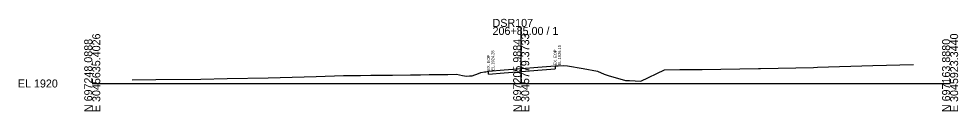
# Model space of a CAD drawing. Extents: x -26 to 19003, y -31 to 24541.
# Drawn here: x 1974.3 to 2302.8, y 15990.3 to 16022.6 of the extents above; entities that cross this region are included whole.
import ezdxf

# ---------------------------------------------------------------- set-up
doc = ezdxf.new("R2010")
doc.units = 0
for name, color, linetype in [('DESIGN - SHEET - Light Grid', 7, 'Continuous'), ('SURVEY - GROUND - Existing Pavement Layer', 7, 'Continuous'), ('SURVEY - GROUND - Existing Pavement Text', 7, 'Continuous'), ('SURVEY - GROUND - Top of Ground', 7, 'Continuous')]:
    doc.layers.add(name, color=color, linetype=linetype)

msp = doc.modelspace()

# ---------------------------------------------------------------- linework, layer by layer
at = {"layer": 'DESIGN - SHEET - Light Grid'}
for p, q in [((2150, 16000), (2150, 16019.79)), ((2000, 16000), (2150, 16000)), ((2150, 16000), (2300, 16000))]:
    msp.add_line(p, q, dxfattribs=at)
at = {"layer": 'SURVEY - GROUND - Existing Pavement Layer'}
for p, q in [((2161.91, 16006.15), (2161.91, 16005.15)), ((2138.56, 16003.28), (2138.56, 16004.28)), ((2138.56, 16003.28), (2144.03, 16003.73)), ((2144.03, 16003.73), (2150.17, 16004.23)), ((2150.17, 16004.23), (2155.85, 16004.68)), ((2155.85, 16004.68), (2161.91, 16005.15))]:
    msp.add_line(p, q, dxfattribs=at)
at = {"layer": 'SURVEY - GROUND - Top of Ground'}
msp.add_lwpolyline([(2013.97, 16001.28), (2022.24, 16001.45), (2037.98, 16001.56), (2047.14, 16001.75), (2061.56, 16002.01), (2078.26, 16002.49), (2087.92, 16002.79), (2089.69, 16002.84), (2093.8, 16002.85), (2097.4, 16002.86), (2101.04, 16002.94), (2105.01, 16002.95), (2111.25, 16003.02), (2114.74, 16003.02), (2117.85, 16003.16), (2120.42, 16003.19), (2124.37, 16003.19), (2127.43, 16003.3), (2129.48, 16002.74), (2130.9, 16002.58), (2131.96, 16002.67), (2132.83, 16002.73), (2135.02, 16003.46), (2135.89, 16003.87), (2137.18, 16004.09), (2137.59, 16004.13), (2138.56, 16004.28), (2144.03, 16004.73), (2150.17, 16005.23), (2155.85, 16005.68), (2161.91, 16006.15), (2162.45, 16006.2), (2162.9, 16006.22), (2164.78, 16006.27), (2166.18, 16006.23), (2171.66, 16005.23), (2176.67, 16004.36), (2179.06, 16003.27), (2180.39, 16002.81), (2181.6, 16002.47), (2185.31, 16001.36), (2186.46, 16000.99), (2187.91, 16001.07), (2191.81, 16000.84), (2200.09, 16004.81), (2205.43, 16004.87), (2212.74, 16004.93), (2213.35, 16004.94), (2232.94, 16005.25), (2233.71, 16005.24), (2252.27, 16005.64), (2253.58, 16005.73), (2272.98, 16006.28), (2287.21, 16006.6)], dxfattribs=at)

# ---------------------------------------------------------------- texts
at = {"layer": 'DESIGN - SHEET - Light Grid'}
for s, p in [('DSR107', (2140, 16019.79)), ('206+85.00 / 1', (2140, 16016.99)), ('EL 1920', (1974, 15998.6))]:
    msp.add_text(s, height=2.8, dxfattribs=at).set_placement(p)
for s, p in [('E 3045635.4026', (2002.8, 15990)), ('E 3045779.3733', (2152.8, 15990)), ('E 3045923.3440', (2302.8, 15990)), ('N 697248.0888', (2000, 15990)), ('N 697205.9884', (2150, 15990)), ('N 697163.8880', (2300, 15990))]:
    msp.add_text(s, height=2.8, rotation=90, dxfattribs=at).set_placement(p)
at = {"layer": 'SURVEY - GROUND - Existing Pavement Text'}
for s, p in [('EL.1926.15', (2163.91, 16006.35)), ('EX. EOP', (2139.06, 16004.48)), ('EL.1924.28', (2140.56, 16004.48)), ('EX. EOP', (2162.41, 16006.35))]:
    msp.add_text(s, height=1, rotation=90, dxfattribs=at).set_placement(p)

doc.saveas('drawing.dxf')
